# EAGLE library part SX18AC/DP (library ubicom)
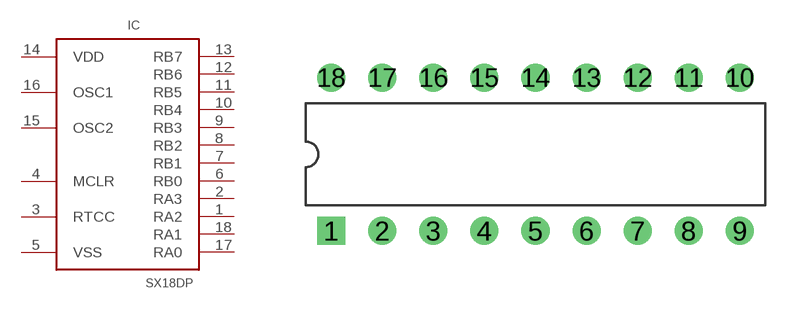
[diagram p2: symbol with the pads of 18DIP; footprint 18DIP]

Designator prefix IC

## SX18AC/DP  [18DIP]
1  RA2
2  RA3
3  RTCC  in
4  MCLR  in
5  VSS  pwr
6  RB0
7  RB1
8  RB2
9  RB3
10  RB4
11  RB5
12  RB6
13  RB7
14  VDD  pwr
15  OSC2  out
16  OSC1  in
17  RA0
18  RA1

## Footprint 18DIP (pad centres in mm)
drill 0.813 pad 1.397 square: 1 -16.192,-3.81
drill 0.813 pad 1.397 round: 2 -13.652,-3.81; 3 -11.113,-3.81; 4 -8.572,-3.81; 5 -6.032,-3.81; 6 -3.493,-3.81; 7 -0.953,-3.81; 8 1.587,-3.81; 9 4.128,-3.81; 10 4.128,3.81; 11 1.587,3.81; 12 -0.953,3.81; 13 -3.493,3.81; 14 -6.032,3.81; 15 -8.572,3.81; 16 -11.113,3.81; 17 -13.652,3.81; 18 -16.192,3.81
